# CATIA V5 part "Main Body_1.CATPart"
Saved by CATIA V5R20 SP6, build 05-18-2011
Part number: Main Body
Bounding box of the stored display mesh (mm): x -86.333 to 86.333, y -63.337 to 9.163, z 0 to 86.333
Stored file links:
  E:\#01 CATIA Lecture Materials\#06 DMU\#04 DMU Page01 KIN EX04\Main Body_1.CATPart
  E:\#01 CATIA Lecture Materials\#06 DMU\#04 DMU Page01 KIN EX04\Main Shaft_1.CATPart
  E:\#01 CATIA Lecture Materials\#06 DMU\#10 Kinematics Joints\#002 Gear Joint(Rotor)\Main Shaft.CATPart
  E:\#01 CATIA Lecture Materials\#06 DMU\#04 DMU Page01 KIN EX04\DMU Page KIN EX04.CATProduct
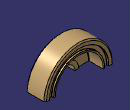
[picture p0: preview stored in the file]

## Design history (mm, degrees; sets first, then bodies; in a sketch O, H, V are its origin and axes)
Set1
  Line1 "Second Rotor Axis": stored without definition
  Line2 "Third Rotor Axis": stored without definition
Body1 (main body)
Body2
  Solid1: solid without history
